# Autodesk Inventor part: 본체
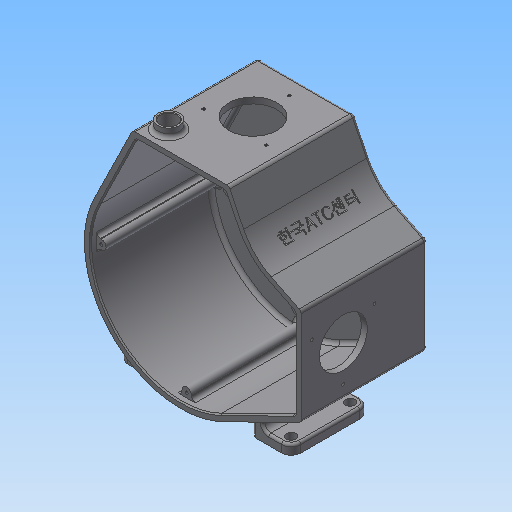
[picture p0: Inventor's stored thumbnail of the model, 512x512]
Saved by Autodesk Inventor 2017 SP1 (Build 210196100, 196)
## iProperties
Created: 2017-05
Part Number: 본체
Material: 알루미늄 6061
Document SubType Name: Modeling
Designer: mduedu
Density: 2.71 g/cm^3
Appearance: 기본값
Mass: 1345.72 g
Surface Area: 1824.08 cm^2
Volume: 496.576 cm^3
Author: mduedu
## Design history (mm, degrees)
sketch "스케치1"
  geometry: L1 (-71.801, 35.28)-(-40, 100); L2 (-40, 100)-(40, 100); L3 (40, 100)-(59.768, 59.768); L4 (59.768, 59.768)-(100, 40); L5 (100, 40)-(100, -40); L6 (100, -40)-(35.28, -71.801); A1 r 80 centre (0, 0) between (-71.801, 35.28) and (35.28, -71.801); 3 further points
  constraints: 12 end point, 4 tangent, 2 midpoint, 2 point on circle, 1 centre point, 1 coincident, 1 horizontal, 1 horizontal alignment, 1 perpendicular, 1 vertical alignment
  dimensions: "d0" = 160 diameter of A1; "d2" = 100 distance from line of L2 point (0, 0); "d3" = 100 distance from line of L5 point (0, 0); "d4" = 80 distance of L1.end L2.end; "d5" = 80 distance of L4.end L5.end
extrude "돌출1" new body sketch "스케치1" distance "d6" = 5; taper "d7" = 0 deg
fillet "모깎기1" dims "d8" = 50
sketch "스케치2"
  geometry: C1 r 22 at (0, 0); 1 further point
  constraints: 1 centre point, 1 coincident
  dimensions: "d9" = 44 diameter of C1
extrude "돌출2" join sketch "스케치2" distance "d10" = 22.5; taper "d11" = 0 deg
sketch "스케치3"
  geometry: C1 r 18.5 at (0, 0); 1 further point
  constraints: 1 centre point, 1 coincident
  dimensions: "d12" = 37 diameter of C1
extrude "돌출3" cut sketch "스케치3" distance "d13" = 9; taper "d14" = 0 deg
fillet "모깎기2" dims "d15" = 3
sketch "스케치4"
  geometry: L1 (35.28, -71.801)-(100, -40) reference; L2 (100, -40)-(100, 40) reference; L3 (100, 40)-(75.073, 52.248) reference; L4 (52.248, 75.073)-(40, 100) reference; L5 (40, 100)-(-40, 100) reference; L6 (-40, 100)-(-71.801, 35.28) reference; L7 (-36.886, 95)-(36.886, 95); L8 (36.886, 95)-(47.76, 72.868); L9 (72.868, 47.76)-(95, 36.886); L10 (95, 36.886)-(95, -36.886); L11 (95, -36.886)-(33.075, -67.313); L12 (-67.313, 33.075)-(-36.886, 95); C1 r 25 at (0, 0) reference; A1 r 50 centre (97.123, 97.123) between (52.248, 75.073) and (75.073, 52.248) reference; A2 r 80 centre (0, 0) between (-71.801, 35.28) and (35.28, -71.801) reference; A3 r 55 centre (97.123, 97.123) between (47.76, 72.868) and (72.868, 47.76); A4 r 75 centre (0, 0) between (-67.313, 33.075) and (33.075, -67.313); 1 further point
  constraints: 12 end point, 4 point on circle, 2 centre point, 7 other
  dimensions: "d16" = 5 distance between parallel lines of L7 L5
extrude "돌출4" join sketch "스케치4" distance "d17" = 100; taper "d18" = 0 deg
sketch "스케치5"
  geometry: L1 (80, 0)-(0, 0) reference; C1 r 20 at (40, -45); 2 further points
  constraints: 1 centre point, 1 midpoint, 1 vertical alignment
  dimensions: "d19" = 40 diameter of C1; "d21" = 45 distance from line of C1.centre L1
extrude "돌출5" cut sketch "스케치5" stored distance "d22" = 100; taper "d23" = 0 deg
sketch "스케치6"
  geometry: L1 (0, 0)-(0, -105) reference; L2 (80, -105)-(0, -105) reference; C1 r 9 at (14, -89); 1 further point
  constraints: 1 centre point
  dimensions: "d24" = 18 diameter of C1; "d26" = 14 distance from line of C1.centre L1; "d27" = 16 distance from line of C1.centre L2
extrude "돌출6" join sketch "스케치6" distance "d28" = 7; taper "d29" = 0 deg
hole "구멍1" diameter "d32" = 14; stored, may be unused: countersink angle "d36" = 90 deg, drill point angle "d38" = 118 deg; dims "d33" = 6, "d34" = 4, "d35" = 2, "d37" = 8, "d39" = 10, "d40" = 10
sketch "스케치7"
  geometry: L1 (-105, 0)-(-105, 80) reference; L2 (0, 0)-(0, 80) reference; C1 r 20 at (-70, 40); 2 further points
  constraints: 1 centre point, 1 horizontal alignment, 1 midpoint
  dimensions: "d41" = 40 diameter of C1; "d42" = 35 distance from line of C1.centre L1
extrude "돌출7" cut sketch "스케치7" stored distance "d43" = 7; taper "d44" = 0 deg
node "작업 평면1"
sketch "스케치8"
  geometry: L1 (47.76, 72.868)-(36.886, 95) reference; L2 (36.886, 95)-(-36.886, 95) reference; L3 (-36.886, 95)-(-67.313, 33.075) reference; L4 (33.075, -67.313)-(95, -36.886) reference; L5 (95, -36.886)-(95, 36.886) reference; L6 (95, 36.886)-(72.868, 47.76) reference; L7 (95, 36.886)-(95, -36.886) reference; L8 (-36.886, 95)-(36.886, 95) reference; L9 (36.886, 95)-(47.76, 72.868) reference; L10 (-71, 4)-(-74.893, 4); L11 (-71, -4)-(-74.893, -4); L12 (-4, -71)-(-4, -74.893); L13 (4, -71)-(4, -74.893); L14 (30.394, 91)-(30.394, 95); L15 (34.394, 87)-(40.817, 87); L16 (30.394, 95)-(36.886, 95); L17 (36.886, 95)-(37.984, 92.764); L18 (91, 30.394)-(95, 30.394); L19 (87, 34.394)-(87, 40.817); L20 (87, 40.817)-(95, 36.886); L21 (95, 36.886)-(95, 30.394); C1 r 25 at (0, 0) reference; A1 r 75 centre (0, 0) between (-67.313, 33.075) and (33.075, -67.313) reference; A2 r 55 centre (97.123, 97.123) between (47.76, 72.868) and (72.868, 47.76) reference; A3 r 4 centre (-71, 0) between (-71, 4) and (-71, -4); A4 r 4 centre (0, -71) between (-4, -71) and (4, -71); A5 r 4 centre (34.394, 91) between (30.394, 91) and (34.394, 87); A6 r 75 centre (0, 0) between (-67.313, 33.075) and (33.075, -67.313) reference; A7 r 4 centre (91, 34.394) between (91, 30.394) and (87, 34.394); 1 further point
  constraints: 24 end point, 17 point on circle, 14 tangent, 5 point on line, 4 centre point, 3 equal radius, 3 perpendicular, 3 vertical, 2 collinear, 2 horizontal, 1 horizontal alignment, 1 parallel, 1 vertical alignment
  dimensions: "d46" = 8 diameter of A3
extrude "돌출8" join sketch "스케치8" stored distance "d49" = 7; taper "d50" = 0 deg
node "작업 평면2"
sketch "스케치9"
  geometry: L1 (71.801, 0)-(71.801, 105) reference; L2 (71.801, 0)-(-35.28, 0) reference; L3 (-35.28, 0)-(-35.28, 105) reference; L4 (71.801, 105)-(-35.28, 105) reference; L5 (40, 0)-(40, 105) reference; L6 (71.801, 52.5)-(-35.28, 52.5); L7 (71.801, 20)-(40, 20); L8 (40, 20)-(40, 85); L9 (40, 85)-(71.801, 85); L10 (71.801, 85)-(71.801, 20); 1 further point
  constraints: 10 end point, 2 midpoint, 2 parallel, 2 point on line, 1 horizontal, 1 perpendicular, 1 other
  dimensions: "d52" = 20 distance between parallel lines of L7 L2
extrude "돌출9" join sketch "스케치9" distance "d53" = 8; taper "d54" = 0 deg
fillet "모깎기3" dims "d55" = 8
sketch "스케치10"
  geometry: C1 r 4 at (-63.801, -28); C2 r 4 at (-63.801, -77); A1 r 8 centre (-63.801, -28) between (-63.801, -20) and (-71.801, -28) reference; A2 r 8 centre (-63.801, -77) between (-71.801, -77) and (-63.801, -85) reference; 1 further point
  constraints: 2 centre point, 2 coincident, 1 equal radius
  dimensions: "d56" = 8 diameter of C1
extrude "돌출10" cut sketch "스케치10" stored distance "d57" = 50.5; taper "d58" = 0 deg
sketch "스케치11"
  geometry: L1 (-63.801, -20)-(-40, -20) reference; L2 (-40, -20)-(-40, -85) reference; L3 (-40, -85)-(-63.801, -85) reference; L4 (-71.801, -77)-(-71.801, -28) reference; L5 (71.801, -77)-(71.801, -28) reference; L6 (40, -85)-(63.801, -85) reference; L7 (40, -20)-(40, -85) reference; L8 (63.801, -20)-(40, -20) reference; L9 (-40, -85)-(-48, -85); L10 (-48, -85)-(-48, -20); L11 (-48, -20)-(-40, -20); L12 (-40, -20)-(-40, -85); L13 (40, -85)-(48, -85); L14 (48, -85)-(48, -20); L15 (48, -20)-(40, -20); L16 (40, -20)-(40, -85); C1 r 4 at (-63.801, -28) reference; C2 r 4 at (-63.801, -77) reference; C3 r 4 at (63.801, -28) reference; C4 r 4 at (63.801, -77) reference; A1 r 8 centre (-63.801, -28) between (-63.801, -20) and (-71.801, -28) reference; A2 r 8 centre (-63.801, -77) between (-71.801, -77) and (-63.801, -85) reference; A3 r 8 centre (63.801, -28) between (71.801, -28) and (63.801, -20) reference; A4 r 8 centre (63.801, -77) between (63.801, -85) and (71.801, -77) reference; 1 further point
  constraints: 16 end point, 4 parallel, 2 horizontal, 2 perpendicular, 2 point on line
  dimensions: "d59" = 8 distance of L10.end L11.end; "d61" = 8 distance of L14.end L15.end
extrude "돌출11" join sketch "스케치11" stored distance "d62" = 5; taper "d63" = 0 deg
fillet "모깎기4" dims "d64" = 5
fillet "모깎기5" dims "d65" = 2
fillet "모깎기6" dims "d66" = 2
fillet "모깎기8" dims "d68" = 2
fillet "모깎기9" dims "d70" = 3, "d101" = 1
fillet "모깎기10" dims "d71" = 3
fillet "모깎기11" dims "d72" = 3
fillet "모깎기12" dims "d73" = 3
fillet "모깎기13" dims "d76" = 3
chamfer "모따기1" distance "d77" = 0.5; stored, may be unused: second distance "d78" = 2, angle "d79" = 45 deg
chamfer "모따기2" distance "d87" = 1; stored, may be unused: second distance "d88" = 2, angle "d89" = 45 deg
chamfer "모따기3" distance "d90" = 1; stored, may be unused: second distance "d91" = 2, angle "d92" = 45 deg
sketch "스케치14"
  geometry: 3 further points
  constraints: 3 other
hole "구멍2" sketch "스케치14" at (-55.375, -40), (-3.414, -40), (-29.394, -85) diameter "d93" = 2.459; stored, may be unused: countersink angle "d97" = 90 deg, drill point angle "d99" = 0 deg; dims "d94" = 6, "d95" = 4, "d96" = 2, "d98" = 8
sketch "스케치15"
  geometry: 3 further points
  constraints: 3 other
hole "구멍4" sketch "스케치15" at (-55.981, -14.394), (-4.019, -14.394), (-30, -59.394) diameter "d102" = 2.459; stored, may be unused: countersink angle "d106" = 90 deg, drill point angle "d108" = 0 deg; dims "d103" = 6, "d104" = 4, "d105" = 2, "d107" = 8
sketch "스케치16"
  geometry: 4 further points
  constraints: 4 other
hole "구멍6" sketch "스케치16" at (0, -71), (91, 34.394), (34.394, 91), (-71, 0) diameter "d109" = 2.459; stored, may be unused: countersink angle "d113" = 90 deg, drill point angle "d115" = 120 deg; dims "d110" = 8.5, "d111" = 4, "d112" = 2, "d114" = 10
node "작업 평면4"
sketch "스케치17"
  geometry: 2 further points
  constraints: 1 horizontal alignment, 1 other
  dimensions: "d116" = 52.5 distance of point (0, 16.14) point (52.5, 16.14)
feature "엠보싱2" sketch "스케치17" dims "d117" = 0.5, "d118" = 0
node "솔리드1"
mirror "대칭1"
node "투영된 루프1"
node "투영된 루프2"
node "투영된 루프3"
node "투영된 루프4"
node "투영된 루프5"
other parameters: "d45" = 95
